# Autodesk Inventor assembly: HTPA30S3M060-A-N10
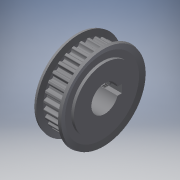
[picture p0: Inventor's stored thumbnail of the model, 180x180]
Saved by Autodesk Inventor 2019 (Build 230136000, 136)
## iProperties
Category: PARTsolutions
Company: MISUMI
Created: 2022-11
Part Number: HTPA30S3M060-A-N10
Catalog Web Link: www.cadenas.de
Description: HTPA__S3M060, HTPA__S3M100, HTPA__S3M150, HTPB__S3M060, HTPB__S3M100, HTPB__S3M150, HTPK__S3M060, HTPK__S3M100, HTPK__S3M150, HTPN__S3M060, HTPN__S3M100, HTPN__
Vendor: MISUMI
Document SubType Name: Assembly
Designer: psAdmin
Manufacturer: MISUMI
Mass: 5.3728 g
Surface Area: 37.292 cm^2
Volume: 5.3728 cm^3
Density: 1 g/cm^3
Title: HTPA30S3M060-A-N10
Author: Cadenas PARTsolutions
Comments: High Torque Timing Pulleys S3M Type
PSOL_IDENT_0: {$CADENAS_DATA/23d-libs/misumi/metric/51_timing_pulleys/htpk_s3m_asmtab.prj},844 {VTYP=3D},{STYP=ASS
PSOL_IDENT_1: TAB},{NB=HTPA30S3M060-A-N10},{LINA=HTPA30S3M060-A-N10},{NN=HTPA__S3M060, HTPA__S3M100, HTPA__S3M150,
PSOL_IDENT_2: HTPB__S3M060, HTPB__S3M100, HTPB__S3M150, HTPK__S3M060, HTPK__S3M100, HTPK__S3M150, HTPN__S3M060, H
PSOL_IDENT_3: TPN__S3M100, HTPN__S3M150, HTPT__S3M060, HTPT__S3M100, HTPT__S3M150, HTPM__S3M060, HTPM__S3M100, HTP
PSOL_IDENT_4: M__S3M150, HTPP__S3M060, HTPP__S3M100, HTPP__S3M150, HTPS__S3M060, HTPS__S3M100, KHTPA__S3M060, KHTP
PSOL_IDENT_5: A__S3M100, KHTPA__S3M150, KHTPK__S3M060, KHTPK__S3M100, KHTPK__S3M150},{DATE=28.10.2022 00:10:07},{G
PSOL_IDENT_6: EOMDATE=15.11.2021 05:07:15},{VERSION=},{LINEID=160},{WBVAR=MATP,ST,TNW,PS,SBS,DD,Z,J,Q,R,S,T,ALT1,A
PSOL_IDENT_7: LT2,M,QSC,QFC,QTC,ALT3,K,KSC,KFC,KTC,ALT4,ZM,ZSC,ZFC,ZTC,ALT5,ALT6,ALT7,FC,ALT8,SRG,ALT9,BTC,TL,ALT1
PSOL_IDENT_8: 0,TPC,ALT11,BC,ALT12,SLH,ALT13,BN},{WBNUMERIC=DD,Z,J,Q,R,S,T,QSC,QFC,QTC,K,KSC,KFC,KTC,ZSC,ZFC,ZTC,F
PSOL_IDENT_9: C,SRG,BTC,TL,BC,SLH,BN}  {NB=HTPA30S3M060-A-N10},{LINA=HTPA30S3M060-A-N10},{KT=DUMMY},{PN=HTPA30S3M0
PSOL_IDENT_10: 60-A-N10},{TYPE=HTPA},{MATP=A2017},{MATPALG='A2017','Aluminum Alloy 2000 series','S45C','1045 Carbon
PSOL_IDENT_11: Steel Equivalent','SUS304','304 Stainless Steel','A6000','6000 Series Aluminum Alloy'},{ST=CA},{STA
PSOL_IDENT_12: LG= 'CA','Clear Anodize','BA','Black Anodize','HAT','Hard Clear Anodize','ENP','Electroless Nickel P
PSOL_IDENT_13: lating' },{NT=30},{TNW=S3M060},{TNWALG= 'S3M060','S3M100','S3M150'    },{BW=6},{PS=A},{PSALG='A','B'
PSOL_IDENT_14: },{SBS=N},{SBSALG= 'H','Round Hole','P','Round Hole + Tap','N','New JIS Keywayed Bore + Tap (Standar
PSOL_IDENT_15: d)','NK','New JIS Keywayed Bore + Tap (width 4.0mm, height 1.8mm)','C','Old JIS Keywayed Bore + Tap'
PSOL_IDENT_16: ,'V','Stepped Hole', 'Y','Both Ends Stepped Hole','WB', 'Double Stepped Hole' },{SHSA= 'H','Round Ho
PSOL_IDENT_17: le','P','Round Hole + Tap','N','New JIS Keywayed Bore + Tap (Standard)','NK','New JIS Keywayed Bore
PSOL_IDENT_18: + Tap (width 4.0mm, height 1.8mm)','C','Old JIS Keywayed Bore + Tap','V','Stepped Hole', 'Y','Both E
PSOL_IDENT_19: nds Stepped Hole','WB', 'Double Stepped Hole' },{SHSB= 'H','Round Hole','P','Round Hole + Tap','N','
PSOL_IDENT_20: New JIS Keywayed Bore + Tap (Standard)','NK','New JIS Keywayed Bore + Tap (width 4.0mm, height 1.8mm
PSOL_IDENT_21: )','C','Old JIS Keywayed Bore + Tap','V','Stepped Hole', 'F','Stepped Hole (Counterbore holes on the
PSOL_IDENT_22: boss side)'},{SHSK= '','' },{SBSPN=-N10},{DD=10.00},{DDALG=[8:8/1],[10:14/1]},{DDHA=[6:6/1],6.35,[7
PSOL_IDENT_23: :12/1],12.7,[13:19/1]},{DDHBK=0},{DDPA=[6:6/1],6.35,[7:12/1],12.7,[13:19/1]},{DDPBK=0},{DDNA=[8:8/1]
PSOL_IDENT_24: ,[10:14/1]},{DDNBK=0},{DDNK=10},{DDCA=[10:10/1],[12:12/1]},{DDCBK=0},{DDVA=[6:6/1],6.35,[7:12/1],12.
PSOL_IDENT_25: 7,[13:17/1]},{DDVF=[6:6/1],6.35,[7:12/1],12.7,[13:14/1]},{DDY=[6:17/1]},{DDWB=[6:15/1]},{Z=0},{ZALG=
PSOL_IDENT_26: [0]},{ZQRMIN=12},{ZAMAX=19},{ZBMAX=16},{DDZ=10},{J=0.0},{JALG=[0]},{JMAX=9},{JMIN=2},{JPN=},{QRMAX=1
PSOL_IDENT_27: 9},{QRMIN=12},{WBRMAX=-2.00},{WBQMIN=14},{Q=0},{QALG=[0]},{QPN=},{R=0},{RALG=[0]},{S=0.0},{SALG=[0]}
PSOL_IDENT_28: ,{SPN=},{SMAX=5},{T=0.0},{TALG=[0]},{TPN=},{TMAX=8},{A=7},{W=11},{L=0},{PD=28.65},{OD=27.89},{D=0},{
PSOL_IDENT_29: DALG=20},{DE=23},{F=32},{E=23},{BBK=3.000},{TTK=1.4},{TT=1},{ANG=120},{WL=11},{ALT1=},{ALT1ALG= '','
PSOL_IDENT_30: w/o KC90 (Set Screw Angle)','KC90','with KC90 (Set Screw Angle)' },{ALT1PN=},{ALT2=},{ALT2ALG= '','N
PSOL_IDENT_31: ot applicable' },{M=N/A},{MALG= 'N/A' },{MFTALG= 'N/A' },{MSALG= 'N/A' },{M3D=0.000},{KDML=0},{ML=0}
PSOL_IDENT_32: ,{MUL=0},{PITCH=0},{QSC=0.0},{QSCALG=0},{QFC=0.0},{QFCALG=0},{QTC=0.0},{QTCALG=0},{QPCDMIN=0},{QPCDM
PSOL_IDENT_33: INALG=0},{QPCDMAX=19},{ALT2PN=},{ALT3=},{ALT3ALG= '','Not applicable' },{K=0.0},{KALG=0},{KMIN=4},{K
PSOL_IDENT_34: FTMAX=0.0},{KSMAX=0.0},{KSC=0.0},{KSCALG=0},{KFC=0.0},{KFCALG=0},{KTC=0.0},{KTCALG=0},{KPCDMIN=14},{
PSOL_IDENT_35: KPCDMINALG=14},{KPCDMAX=19},{KSCMIN=14.0},{KSCMINALG=14},{ALT3PN=},{ALT4=},{ALT4ALG= '','Not applica
PSOL_IDENT_36: ble' },{ALT4MIN=20.5},{ALT4MAX=12.5},{ZM=N/A},{ZMALG= 'N/A' },{ZMSALG= 'N/A' },{ZMFTALG= 'N/A' },{ZM
PSOL_IDENT_37: DD1=0.0},{ZMDD2=0.0},{ZMHH=0.0},{ZSC=0.0},{ZSCALG=[0]},{ZFC=0.0},{ZFCALG=[0]},{ZTC=0.0},{ZTCALG=[0]}
PSOL_IDENT_38: ,{ZPCDMIN=0},{ZPCDMINALG=0},{ZPCDMAX=19},{ALT4PN=},{ALT5=},{ALT5ALG= '','Flange Attached','NFC','wit
PSOL_IDENT_39: h NFC (Flange not Attached)' },{ALT5PN=},{ALT6=},{ALT6ALG= '','w/o Flange Attached on One Side Only'
PSOL_IDENT_40: ,'RFC','with RFC (Flange Attached on The Boss Side Only)','LFC','with LFC (Flange Attached on The Op
PSOL_IDENT_41: posite Side Only)' },{ALT6PN=},{ALT7=},{ALT7ALG= '','w/o FC (Flange Cut)','FC','with FC (Flange Cut)'
PSOL_IDENT_42: },{FC=0.0},{FCALG=0},{FCMIN=29.0},{FCMAX=30.0},{ALT7PN=},{ALT8=},{ALT8ALG= '','Not applicable' },{A
PSOL_IDENT_43: LT8ALGALG=19},{ALT8DD2=0},{ALT8MM=0},{ALT8NN=0},{QC=0},{KC=0},{ZC=0},{SRG=0.0},{SRGALG=[0]},{SRGMAX1=
PSOL_IDENT_44: 0},{SRGMAX=0},{DD2=0.0},{MM=0.00},{NN=0.00},{ALT8PN=},{ALT9ALG= '','Not applicable' },{ALT9=},{BTC9=
PSOL_IDENT_45: 11},{TL9=1},{BTC=0},{BTCALG=[0]},{TL=0.0},{TLALG=0},{TLMIN=1.0},{TLMAX=-11.5},{BTCL=0},{BTCD=0},{BTC
PSOL_IDENT_46: DALG=20.000},{ALT9PN=},{WLBCTL=11},{ALT10=},{ALT10ALG= '','w/o TPC (Tapped Hole Dimension)','TPC','w
PSOL_IDENT_47: ith TPC (Tapped Hole Dimension)' },{TPC=N/A},{TPCALG= 'N/A' },{TPCM=4},{ALT10PN=},{ALT11=},{ALT11ALG=
PSOL_IDENT_48: '','Not applicable' },{BC=0.0},{BCALG=0},{BCMIN=7},{BCMAX=-11.5},{BCPLANE=5.5},{M1WBC=5.5},{ALT11PN=
PSOL_IDENT_49: },{ALT12=},{ALT12ALG= '','w/o SLH (Set Screw Length)','SLH','with SLH (Set Screw Length)' },{SLH=0},
PSOL_IDENT_50: {SLHALG=[0]},{ALT12PN=},{AC=M4x3},{M1=4},{M1L=3},{TAP=0.000},{KYY=5},{KTT=8.945},{PLANE=11},{ALT13=}
PSOL_IDENT_51: ,{ALT13ALG= '', 'Not applicable' },{BN=0.0},{BNALG=0},{BNMIN=-10.5},{BNMAX=-1.0},{ALT13PN=},{PPATH=h
PSOL_IDENT_52: tpk_s3m/htpa_s3m_asmtpl.prj}
NB: HTPA30S3M060-A-N10
NN: 0
NT: 30
NBSYN: $PN.
LINA: HTPA30S3M060-A-N10
CATALOG: Misumi
PN: HTPA30S3M060-A-N10
MATP: Aluminum Alloy 2000 series
ST: Clear Anodize
TNW: S3M060
BW: 6
PS: A
SBS: New JIS Keywayed Bore + Tap (Standard)
DD: 10
Z: 0
J: 0
Q: 0
R: 0
S: 0
T: 0
A: 7
W: 11
L: 0
PD: 28.65
OD: 27.89
D: 0
F: 32
E: 23
TT: 1
ALT1: w/o KC90 (Set Screw Angle)
ALT2: Not applicable
M: N/A
QSC: 0
QFC: 0
QTC: 0
ALT3: Not applicable
K: 0
KSC: 0
KFC: 0
KTC: 0
ALT4: Not applicable
ZM: N/A
ZMDD1: 0
ZMDD2: 0
ZMHH: 0
ZSC: 0
ZFC: 0
ZTC: 0
ALT5: Flange Attached
ALT6: w/o Flange Attached on One Side Only
ALT7: w/o FC (Flange Cut)
FC: 0
ALT8: Not applicable
SRG: 0
DD2: 0
MM: 0
ALT9: Not applicable
BTC: 0
TL: 0
BTCL: 0
BTCD: 0
ALT10: w/o TPC (Tapped Hole Dimension)
TPC: N/A
ALT11: Not applicable
BC: 0
ALT12: w/o SLH (Set Screw Length)
SLH: 0
AC: M4x3
ALT13: Not applicable
BN: 0
SUPPLIER: MISUMI
ARTICLENO: HTPA30S3M060-A-N10
BOMINFO: HTPA30S3M060-A-N10
CREATOR: CADENAS GmbH
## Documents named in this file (3)
- e:\temp\worker_COMMON_8\temp\tmp_7176_226_jI4QF\format_0\HTPA30S3M060-A-N10.iam
- e:\temp\worker_COMMON_8\temp\tmp_7176_226_jI4QF\format_0\HTPA30S3M060-A-N10_b.ipt
- e:\temp\worker_COMMON_8\temp\tmp_7176_226_jI4QF\format_0\SET-SCREW4-3.ipt
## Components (3 placed, 2 different names)
1. HTPA30S3M060-A-N10_b:1 — to_screw1_XY@1 <-> CP_XY@2, to_screw1_Z@1 <-> CP_Z@2, to_screw1_YZ@1 <-> CP_YZ@2, to_screw2_XY@1 <-> CP_XY@3, to_screw2_Z@1 <-> CP_Z@3, to_screw2_YZ@1 <-> CP_YZ@3
2. SET-SCREW4-3:1 — to_screw1_XY@1 <-> CP_XY@2, to_screw1_Z@1 <-> CP_Z@2, to_screw1_YZ@1 <-> CP_YZ@2
3. SET-SCREW4-3:2 — to_screw2_XY@1 <-> CP_XY@3, to_screw2_Z@1 <-> CP_Z@3, to_screw2_YZ@1 <-> CP_YZ@3
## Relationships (6: Mate 4, Angle 2)
- to_screw1_XY@1 <-> CP_XY@2 [Mate]: HTPA30S3M060-A-N10_b:1 ↔ SET-SCREW4-3:1
- to_screw1_Z@1 <-> CP_Z@2 [Mate]: HTPA30S3M060-A-N10_b:1 ↔ SET-SCREW4-3:1
- to_screw1_YZ@1 <-> CP_YZ@2 [Angle]: HTPA30S3M060-A-N10_b:1 ↔ SET-SCREW4-3:1
- to_screw2_XY@1 <-> CP_XY@3 [Mate]: HTPA30S3M060-A-N10_b:1 ↔ SET-SCREW4-3:2
- to_screw2_Z@1 <-> CP_Z@3 [Mate]: HTPA30S3M060-A-N10_b:1 ↔ SET-SCREW4-3:2
- to_screw2_YZ@1 <-> CP_YZ@3 [Angle]: HTPA30S3M060-A-N10_b:1 ↔ SET-SCREW4-3:2
